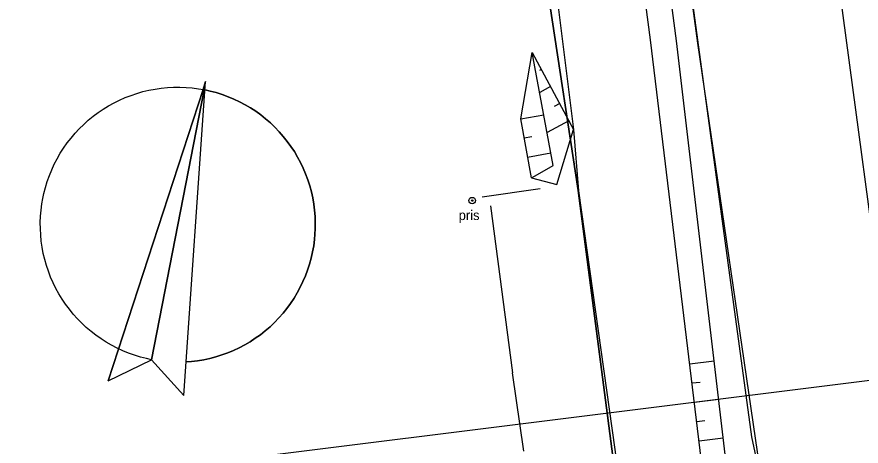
# Model space of a CAD drawing. Extents: x -555887 to -552101, y -1100251 to -1096546.
# Drawn here: x -554065.2 to -553999.8, y -1097845.2 to -1097812 of the extents above; entities that cross this region are included whole.
import ezdxf

# ---------------------------------------------------------------- set-up
doc = ezdxf.new("R2010")
doc.units = 0
for name, color, linetype in [('07_VODOVOD', 7, 'Continuous'), ('PARCELY_silnice', 7, 'Continuous'), ('ROZHLED_ram_legenda_1', 7, 'Continuous'), ('ZSST', 7, 'Continuous'), ('zájem', 7, 'Continuous')]:
    doc.layers.add(name, color=color, linetype=linetype)

msp = doc.modelspace()

# ---------------------------------------------------------------- linework, layer by layer
at = {"layer": '07_VODOVOD'}
msp.add_lwpolyline([(-553936.175, -1098296.386), (-554003.21, -1097797.26), (-554016.58, -1097798.55), (-554021.42, -1097763.29), (-554007.81, -1097761.46), (-554017.883, -1097690.586), (-554019.47, -1097678.04), (-553931.71, -1097666.8), (-553860.51, -1097660.95), (-553851.186, -1097659.979), (-553809.175, -1097658.756), (-553772.306, -1097657.572), (-553745.69, -1097656.809), (-553714.889, -1097655.5), (-553705.569, -1097655.382), (-553663.409, -1097654.214), (-553621.83, -1097652.811), (-553564.872, -1097648.296)], dxfattribs=at)
at = {"layer": 'PARCELY_silnice'}
for points in [[(-553950.34, -1098288.41), (-554001.81, -1097900.62), (-554000.01, -1097890.44), (-554002.33, -1097872.53), (-554008.3, -1097844.49), (-554029.64, -1097687.62), (-554030.91, -1097678.33), (-554047.02, -1097559.88)], [(-554053.21, -1097604.42), (-554046.53, -1097659.36), (-554040.57, -1097685.1), (-554037.19, -1097711.74), (-554032.71, -1097743.24), (-554030.08, -1097764.38), (-554029.42, -1097766.27), (-554026.13, -1097796.62), (-554021.75, -1097825.43), (-554018.68, -1097848.98), (-554014.41, -1097881.75), (-554013.24, -1097889.61), (-554000.89, -1097984.42), (-553998.62, -1098003.87), (-553997.67, -1098021.07), (-553963.01, -1098289.11)]]:
    msp.add_lwpolyline(points, dxfattribs=at)
at = {"layer": 'ROZHLED_ram_legenda_1'}
for p, q in [((-554052.28, -1097841.301), (-554050.582, -1097816.99)), ((-554050.782, -1097817.613), (-554050.582, -1097816.99)), ((-554050.782, -1097817.613), (-554050.582, -1097816.99)), ((-554050.782, -1097817.613), (-554050.582, -1097816.99)), ((-554050.782, -1097817.613), (-554050.582, -1097816.99)), ((-554050.782, -1097817.613), (-554050.582, -1097816.99)), ((-554050.782, -1097817.613), (-554050.582, -1097816.99)), ((-554050.782, -1097817.613), (-554050.582, -1097816.99)), ((-554050.782, -1097817.613), (-554050.582, -1097816.99)), ((-554050.706, -1097817.628), (-554050.582, -1097816.99)), ((-554050.706, -1097817.628), (-554050.582, -1097816.99)), ((-554050.706, -1097817.628), (-554050.582, -1097816.99)), ((-554050.706, -1097817.628), (-554050.582, -1097816.99)), ((-554050.706, -1097817.628), (-554050.582, -1097816.99)), ((-554050.706, -1097817.628), (-554050.582, -1097816.99)), ((-554050.706, -1097817.628), (-554050.582, -1097816.99)), ((-554050.706, -1097817.628), (-554050.582, -1097816.99)), ((-554058.115, -1097840.167), (-554050.782, -1097817.613)), ((-554050.706, -1097817.628), (-554054.768, -1097838.523)), ((-554054.767, -1097838.522), (-554052.28, -1097841.3))]:
    msp.add_line(p, q, dxfattribs=at)
for points in [[(-554134.234, -1097857.005), (-554169.828, -1097572.221), (-553971.373, -1097547.416), (-553935.778, -1097832.201), (-554134.234, -1097857.005)], [(-554134.234, -1097857.005), (-554169.828, -1097572.221), (-553971.373, -1097547.416), (-553935.778, -1097832.201), (-554134.234, -1097857.005)], [(-554054.767, -1097838.522), (-554055.171, -1097838.437), (-554055.637, -1097838.316), (-554056.097, -1097838.174), (-554056.55, -1097838.012), (-554056.995, -1097837.83), (-554057.431, -1097837.627), (-554057.858, -1097837.405), (-554058.275, -1097837.165), (-554058.68, -1097836.905), (-554059.073, -1097836.627), (-554059.453, -1097836.332), (-554059.819, -1097836.02), (-554060.171, -1097835.692), (-554060.507, -1097835.349), (-554060.828, -1097834.99), (-554061.132, -1097834.617), (-554061.419, -1097834.231), (-554061.689, -1097833.832), (-554061.94, -1097833.422), (-554062.172, -1097833.001), (-554062.385, -1097832.569), (-554062.578, -1097832.129), (-554062.751, -1097831.68), (-554062.904, -1097831.224), (-554063.036, -1097830.761), (-554063.146, -1097830.293), (-554063.236, -1097829.82), (-554063.304, -1097829.344), (-554063.351, -1097828.865), (-554063.376, -1097828.385), (-554063.379, -1097827.904), (-554063.36, -1097827.423), (-554063.32, -1097826.943), (-554063.258, -1097826.466), (-554063.186, -1097826.059), (-554063.101, -1097825.655), (-554062.981, -1097825.189), (-554062.84, -1097824.729), (-554062.679, -1097824.276), (-554062.497, -1097823.831), (-554062.295, -1097823.394), (-554062.074, -1097822.967), (-554061.834, -1097822.55), (-554061.575, -1097822.144), (-554061.298, -1097821.751), (-554061.003, -1097821.371), (-554060.692, -1097821.004), (-554060.364, -1097820.652), (-554060.021, -1097820.315), (-554059.663, -1097819.993), (-554059.29, -1097819.689), (-554058.905, -1097819.401), (-554058.506, -1097819.131), (-554058.096, -1097818.88), (-554057.675, -1097818.647), (-554057.244, -1097818.433), (-554056.804, -1097818.239), (-554056.355, -1097818.066), (-554055.899, -1097817.912), (-554055.437, -1097817.78), (-554054.969, -1097817.668), (-554054.496, -1097817.578), (-554054.02, -1097817.509), (-554053.541, -1097817.462), (-554053.061, -1097817.436), (-554052.58, -1097817.433), (-554052.099, -1097817.451), (-554051.62, -1097817.49), (-554051.143, -1097817.551), (-554050.736, -1097817.623)], [(-554050.628, -1097817.644), (-554050.223, -1097817.732), (-554049.756, -1097817.857), (-554049.295, -1097818.003), (-554048.841, -1097818.17), (-554048.395, -1097818.357), (-554047.958, -1097818.565), (-554047.531, -1097818.791), (-554047.114, -1097819.037), (-554046.709, -1097819.302), (-554046.317, -1097819.585), (-554045.938, -1097819.885), (-554045.573, -1097820.203), (-554045.223, -1097820.536), (-554044.888, -1097820.885), (-554044.57, -1097821.249), (-554044.268, -1097821.627), (-554043.984, -1097822.019), (-554043.718, -1097822.422), (-554043.47, -1097822.838), (-554043.242, -1097823.264), (-554043.033, -1097823.701), (-554042.844, -1097824.146), (-554042.676, -1097824.599), (-554042.529, -1097825.06), (-554042.402, -1097825.527), (-554042.297, -1097825.999), (-554042.214, -1097826.475), (-554042.152, -1097826.955), (-554042.112, -1097827.437), (-554042.094, -1097827.92), (-554042.098, -1097828.404), (-554042.12, -1097828.818), (-554042.156, -1097829.23), (-554042.219, -1097829.71), (-554042.304, -1097830.186), (-554042.411, -1097830.658), (-554042.539, -1097831.124), (-554042.688, -1097831.584), (-554042.858, -1097832.037), (-554043.048, -1097832.482), (-554043.258, -1097832.917), (-554043.488, -1097833.343), (-554043.736, -1097833.758), (-554044.004, -1097834.161), (-554044.289, -1097834.551), (-554044.592, -1097834.928), (-554044.912, -1097835.291), (-554045.248, -1097835.639), (-554045.599, -1097835.971), (-554045.965, -1097836.287), (-554046.345, -1097836.586), (-554046.738, -1097836.868), (-554047.144, -1097837.131), (-554047.561, -1097837.376), (-554047.989, -1097837.602), (-554048.427, -1097837.807), (-554048.873, -1097837.993), (-554049.328, -1097838.158), (-554049.789, -1097838.303), (-554050.257, -1097838.426), (-554050.73, -1097838.528), (-554051.207, -1097838.608), (-554051.687, -1097838.667), (-554052.1, -1097838.698)], [(-554052.1, -1097838.698), (-554051.687, -1097838.667), (-554051.207, -1097838.608), (-554050.73, -1097838.528), (-554050.257, -1097838.426), (-554049.789, -1097838.303), (-554049.328, -1097838.158), (-554048.873, -1097837.993), (-554048.427, -1097837.807), (-554047.989, -1097837.602), (-554047.561, -1097837.376), (-554047.144, -1097837.131), (-554046.738, -1097836.868), (-554046.345, -1097836.586), (-554045.965, -1097836.287), (-554045.599, -1097835.971), (-554045.248, -1097835.639), (-554044.912, -1097835.291), (-554044.592, -1097834.928), (-554044.289, -1097834.551), (-554044.004, -1097834.161), (-554043.736, -1097833.758), (-554043.488, -1097833.343), (-554043.258, -1097832.917), (-554043.048, -1097832.482), (-554042.858, -1097832.037), (-554042.688, -1097831.584), (-554042.539, -1097831.124), (-554042.411, -1097830.658), (-554042.304, -1097830.186), (-554042.219, -1097829.71), (-554042.156, -1097829.23), (-554042.12, -1097828.818), (-554042.098, -1097828.404), (-554042.094, -1097827.92), (-554042.112, -1097827.437), (-554042.152, -1097826.955), (-554042.214, -1097826.475), (-554042.297, -1097825.999), (-554042.402, -1097825.527), (-554042.529, -1097825.06), (-554042.676, -1097824.599), (-554042.844, -1097824.146), (-554043.033, -1097823.701), (-554043.242, -1097823.264), (-554043.47, -1097822.838), (-554043.718, -1097822.422), (-554043.984, -1097822.019), (-554044.268, -1097821.627), (-554044.57, -1097821.249), (-554044.888, -1097820.885), (-554045.223, -1097820.536), (-554045.573, -1097820.203), (-554045.938, -1097819.885), (-554046.317, -1097819.585), (-554046.709, -1097819.302), (-554047.114, -1097819.037), (-554047.531, -1097818.791), (-554047.958, -1097818.565), (-554048.395, -1097818.357), (-554048.841, -1097818.17), (-554049.295, -1097818.003), (-554049.756, -1097817.857), (-554050.223, -1097817.732), (-554050.628, -1097817.644)], [(-554052.1, -1097838.698), (-554051.687, -1097838.667), (-554051.207, -1097838.608), (-554050.73, -1097838.528), (-554050.257, -1097838.426), (-554049.789, -1097838.303), (-554049.328, -1097838.158), (-554048.873, -1097837.993), (-554048.427, -1097837.807), (-554047.989, -1097837.602), (-554047.561, -1097837.376), (-554047.144, -1097837.131), (-554046.738, -1097836.868), (-554046.345, -1097836.586), (-554045.965, -1097836.287), (-554045.599, -1097835.971), (-554045.248, -1097835.639), (-554044.912, -1097835.291), (-554044.592, -1097834.928), (-554044.289, -1097834.551), (-554044.004, -1097834.161), (-554043.736, -1097833.758), (-554043.488, -1097833.343), (-554043.258, -1097832.917), (-554043.048, -1097832.482), (-554042.858, -1097832.037), (-554042.688, -1097831.584), (-554042.539, -1097831.124), (-554042.411, -1097830.658), (-554042.304, -1097830.186), (-554042.219, -1097829.71), (-554042.156, -1097829.23), (-554042.12, -1097828.818), (-554042.098, -1097828.404), (-554042.094, -1097827.92), (-554042.112, -1097827.437), (-554042.152, -1097826.955), (-554042.214, -1097826.475), (-554042.297, -1097825.999), (-554042.402, -1097825.527), (-554042.529, -1097825.06), (-554042.676, -1097824.599), (-554042.844, -1097824.146), (-554043.033, -1097823.701), (-554043.242, -1097823.264), (-554043.47, -1097822.838), (-554043.718, -1097822.422), (-554043.984, -1097822.019), (-554044.268, -1097821.627), (-554044.57, -1097821.249), (-554044.888, -1097820.885), (-554045.223, -1097820.536), (-554045.573, -1097820.203), (-554045.938, -1097819.885), (-554046.317, -1097819.585), (-554046.709, -1097819.302), (-554047.114, -1097819.037), (-554047.531, -1097818.791), (-554047.958, -1097818.565), (-554048.395, -1097818.357), (-554048.841, -1097818.17), (-554049.295, -1097818.003), (-554049.756, -1097817.857), (-554050.223, -1097817.732), (-554050.628, -1097817.644)], [(-554052.1, -1097838.698), (-554051.687, -1097838.667), (-554051.207, -1097838.608), (-554050.73, -1097838.528), (-554050.257, -1097838.426), (-554049.789, -1097838.303), (-554049.328, -1097838.158), (-554048.873, -1097837.993), (-554048.427, -1097837.807), (-554047.989, -1097837.602), (-554047.561, -1097837.376), (-554047.144, -1097837.131), (-554046.738, -1097836.868), (-554046.345, -1097836.586), (-554045.965, -1097836.287), (-554045.599, -1097835.971), (-554045.248, -1097835.639), (-554044.912, -1097835.291), (-554044.592, -1097834.928), (-554044.289, -1097834.551), (-554044.004, -1097834.161), (-554043.736, -1097833.758), (-554043.488, -1097833.343), (-554043.258, -1097832.917), (-554043.048, -1097832.482), (-554042.858, -1097832.037), (-554042.688, -1097831.584), (-554042.539, -1097831.124), (-554042.411, -1097830.658), (-554042.304, -1097830.186), (-554042.219, -1097829.71), (-554042.156, -1097829.23), (-554042.12, -1097828.818), (-554042.098, -1097828.404), (-554042.094, -1097827.92), (-554042.112, -1097827.437), (-554042.152, -1097826.955), (-554042.214, -1097826.475), (-554042.297, -1097825.999), (-554042.402, -1097825.527), (-554042.529, -1097825.06), (-554042.676, -1097824.599), (-554042.844, -1097824.146), (-554043.033, -1097823.701), (-554043.242, -1097823.264), (-554043.47, -1097822.838), (-554043.718, -1097822.422), (-554043.984, -1097822.019), (-554044.268, -1097821.627), (-554044.57, -1097821.249), (-554044.888, -1097820.885), (-554045.223, -1097820.536), (-554045.573, -1097820.203), (-554045.938, -1097819.885), (-554046.317, -1097819.585), (-554046.709, -1097819.302), (-554047.114, -1097819.037), (-554047.531, -1097818.791), (-554047.958, -1097818.565), (-554048.395, -1097818.357), (-554048.841, -1097818.17), (-554049.295, -1097818.003), (-554049.756, -1097817.857), (-554050.223, -1097817.732), (-554050.628, -1097817.644)], [(-554052.1, -1097838.698), (-554051.687, -1097838.667), (-554051.207, -1097838.608), (-554050.73, -1097838.528), (-554050.257, -1097838.426), (-554049.789, -1097838.303), (-554049.328, -1097838.158), (-554048.873, -1097837.993), (-554048.427, -1097837.807), (-554047.989, -1097837.602), (-554047.561, -1097837.376), (-554047.144, -1097837.131), (-554046.738, -1097836.868), (-554046.345, -1097836.586), (-554045.965, -1097836.287), (-554045.599, -1097835.971), (-554045.248, -1097835.639), (-554044.912, -1097835.291), (-554044.592, -1097834.928), (-554044.289, -1097834.551), (-554044.004, -1097834.161), (-554043.736, -1097833.758), (-554043.488, -1097833.343), (-554043.258, -1097832.917), (-554043.048, -1097832.482), (-554042.858, -1097832.037), (-554042.688, -1097831.584), (-554042.539, -1097831.124), (-554042.411, -1097830.658), (-554042.304, -1097830.186), (-554042.219, -1097829.71), (-554042.156, -1097829.23), (-554042.12, -1097828.818), (-554042.098, -1097828.404), (-554042.094, -1097827.92), (-554042.112, -1097827.437), (-554042.152, -1097826.955), (-554042.214, -1097826.475), (-554042.297, -1097825.999), (-554042.402, -1097825.527), (-554042.529, -1097825.06), (-554042.676, -1097824.599), (-554042.844, -1097824.146), (-554043.033, -1097823.701), (-554043.242, -1097823.264), (-554043.47, -1097822.838), (-554043.718, -1097822.422), (-554043.984, -1097822.019), (-554044.268, -1097821.627), (-554044.57, -1097821.249), (-554044.888, -1097820.885), (-554045.223, -1097820.536), (-554045.573, -1097820.203), (-554045.938, -1097819.885), (-554046.317, -1097819.585), (-554046.709, -1097819.302), (-554047.114, -1097819.037), (-554047.531, -1097818.791), (-554047.958, -1097818.565), (-554048.395, -1097818.357), (-554048.841, -1097818.17), (-554049.295, -1097818.003), (-554049.756, -1097817.857), (-554050.223, -1097817.732), (-554050.628, -1097817.644)], [(-554052.1, -1097838.698), (-554051.687, -1097838.667), (-554051.207, -1097838.608), (-554050.73, -1097838.528), (-554050.257, -1097838.426), (-554049.789, -1097838.303), (-554049.328, -1097838.158), (-554048.873, -1097837.993), (-554048.427, -1097837.807), (-554047.989, -1097837.602), (-554047.561, -1097837.376), (-554047.144, -1097837.131), (-554046.738, -1097836.868), (-554046.345, -1097836.586), (-554045.965, -1097836.287), (-554045.599, -1097835.971), (-554045.248, -1097835.639), (-554044.912, -1097835.291), (-554044.592, -1097834.928), (-554044.289, -1097834.551), (-554044.004, -1097834.161), (-554043.736, -1097833.758), (-554043.488, -1097833.343), (-554043.258, -1097832.917), (-554043.048, -1097832.482), (-554042.858, -1097832.037), (-554042.688, -1097831.584), (-554042.539, -1097831.124), (-554042.411, -1097830.658), (-554042.304, -1097830.186), (-554042.219, -1097829.71), (-554042.156, -1097829.23), (-554042.12, -1097828.818), (-554042.098, -1097828.404), (-554042.094, -1097827.92), (-554042.112, -1097827.437), (-554042.152, -1097826.955), (-554042.214, -1097826.475), (-554042.297, -1097825.999), (-554042.402, -1097825.527), (-554042.529, -1097825.06), (-554042.676, -1097824.599), (-554042.844, -1097824.146), (-554043.033, -1097823.701), (-554043.242, -1097823.264), (-554043.47, -1097822.838), (-554043.718, -1097822.422), (-554043.984, -1097822.019), (-554044.268, -1097821.627), (-554044.57, -1097821.249), (-554044.888, -1097820.885), (-554045.223, -1097820.536), (-554045.573, -1097820.203), (-554045.938, -1097819.885), (-554046.317, -1097819.585), (-554046.709, -1097819.302), (-554047.114, -1097819.037), (-554047.531, -1097818.791), (-554047.958, -1097818.565), (-554048.395, -1097818.357), (-554048.841, -1097818.17), (-554049.295, -1097818.003), (-554049.756, -1097817.857), (-554050.223, -1097817.732), (-554050.628, -1097817.644)], [(-554052.1, -1097838.698), (-554051.687, -1097838.667), (-554051.207, -1097838.608), (-554050.73, -1097838.528), (-554050.257, -1097838.426), (-554049.789, -1097838.303), (-554049.328, -1097838.158), (-554048.873, -1097837.993), (-554048.427, -1097837.807), (-554047.989, -1097837.602), (-554047.561, -1097837.376), (-554047.144, -1097837.131), (-554046.738, -1097836.868), (-554046.345, -1097836.586), (-554045.965, -1097836.287), (-554045.599, -1097835.971), (-554045.248, -1097835.639), (-554044.912, -1097835.291), (-554044.592, -1097834.928), (-554044.289, -1097834.551), (-554044.004, -1097834.161), (-554043.736, -1097833.758), (-554043.488, -1097833.343), (-554043.258, -1097832.917), (-554043.048, -1097832.482), (-554042.858, -1097832.037), (-554042.688, -1097831.584), (-554042.539, -1097831.124), (-554042.411, -1097830.658), (-554042.304, -1097830.186), (-554042.219, -1097829.71), (-554042.156, -1097829.23), (-554042.12, -1097828.818), (-554042.098, -1097828.404), (-554042.094, -1097827.92), (-554042.112, -1097827.437), (-554042.152, -1097826.955), (-554042.214, -1097826.475), (-554042.297, -1097825.999), (-554042.402, -1097825.527), (-554042.529, -1097825.06), (-554042.676, -1097824.599), (-554042.844, -1097824.146), (-554043.033, -1097823.701), (-554043.242, -1097823.264), (-554043.47, -1097822.838), (-554043.718, -1097822.422), (-554043.984, -1097822.019), (-554044.268, -1097821.627), (-554044.57, -1097821.249), (-554044.888, -1097820.885), (-554045.223, -1097820.536), (-554045.573, -1097820.203), (-554045.938, -1097819.885), (-554046.317, -1097819.585), (-554046.709, -1097819.302), (-554047.114, -1097819.037), (-554047.531, -1097818.791), (-554047.958, -1097818.565), (-554048.395, -1097818.357), (-554048.841, -1097818.17), (-554049.295, -1097818.003), (-554049.756, -1097817.857), (-554050.223, -1097817.732), (-554050.628, -1097817.644)], [(-554052.1, -1097838.698), (-554051.687, -1097838.667), (-554051.207, -1097838.608), (-554050.73, -1097838.528), (-554050.257, -1097838.426), (-554049.789, -1097838.303), (-554049.328, -1097838.158), (-554048.873, -1097837.993), (-554048.427, -1097837.807), (-554047.989, -1097837.602), (-554047.561, -1097837.376), (-554047.144, -1097837.131), (-554046.738, -1097836.868), (-554046.345, -1097836.586), (-554045.965, -1097836.287), (-554045.599, -1097835.971), (-554045.248, -1097835.639), (-554044.912, -1097835.291), (-554044.592, -1097834.928), (-554044.289, -1097834.551), (-554044.004, -1097834.161), (-554043.736, -1097833.758), (-554043.488, -1097833.343), (-554043.258, -1097832.917), (-554043.048, -1097832.482), (-554042.858, -1097832.037), (-554042.688, -1097831.584), (-554042.539, -1097831.124), (-554042.411, -1097830.658), (-554042.304, -1097830.186), (-554042.219, -1097829.71), (-554042.156, -1097829.23), (-554042.12, -1097828.818), (-554042.098, -1097828.404), (-554042.094, -1097827.92), (-554042.112, -1097827.437), (-554042.152, -1097826.955), (-554042.214, -1097826.475), (-554042.297, -1097825.999), (-554042.402, -1097825.527), (-554042.529, -1097825.06), (-554042.676, -1097824.599), (-554042.844, -1097824.146), (-554043.033, -1097823.701), (-554043.242, -1097823.264), (-554043.47, -1097822.838), (-554043.718, -1097822.422), (-554043.984, -1097822.019), (-554044.268, -1097821.627), (-554044.57, -1097821.249), (-554044.888, -1097820.885), (-554045.223, -1097820.536), (-554045.573, -1097820.203), (-554045.938, -1097819.885), (-554046.317, -1097819.585), (-554046.709, -1097819.302), (-554047.114, -1097819.037), (-554047.531, -1097818.791), (-554047.958, -1097818.565), (-554048.395, -1097818.357), (-554048.841, -1097818.17), (-554049.295, -1097818.003), (-554049.756, -1097817.857), (-554050.223, -1097817.732), (-554050.628, -1097817.644)]]:
    msp.add_lwpolyline(points, dxfattribs=at)
for points in [[(-554050.784, -1097817.613), (-554050.764, -1097817.617), (-554050.745, -1097817.621), (-554050.725, -1097817.625), (-554050.706, -1097817.628), (-554050.706, -1097817.628), (-554050.582, -1097816.99), (-554050.782, -1097817.613), (-554050.782, -1097817.613)], [(-554050.784, -1097817.613), (-554050.764, -1097817.617), (-554050.745, -1097817.621), (-554050.725, -1097817.625), (-554050.706, -1097817.628), (-554050.706, -1097817.628), (-554050.582, -1097816.99), (-554050.782, -1097817.613), (-554050.782, -1097817.613)], [(-554050.784, -1097817.613), (-554050.764, -1097817.617), (-554050.745, -1097817.621), (-554050.725, -1097817.625), (-554050.706, -1097817.628), (-554050.706, -1097817.628), (-554050.582, -1097816.99), (-554050.782, -1097817.613), (-554050.782, -1097817.613)], [(-554050.784, -1097817.613), (-554050.764, -1097817.617), (-554050.745, -1097817.621), (-554050.725, -1097817.625), (-554050.706, -1097817.628), (-554050.706, -1097817.628), (-554050.582, -1097816.99), (-554050.782, -1097817.613), (-554050.782, -1097817.613)], [(-554050.784, -1097817.613), (-554050.764, -1097817.617), (-554050.745, -1097817.621), (-554050.725, -1097817.625), (-554050.706, -1097817.628), (-554050.706, -1097817.628), (-554050.582, -1097816.99), (-554050.782, -1097817.613), (-554050.782, -1097817.613)], [(-554050.784, -1097817.613), (-554050.764, -1097817.617), (-554050.745, -1097817.621), (-554050.725, -1097817.625), (-554050.706, -1097817.628), (-554050.706, -1097817.628), (-554050.582, -1097816.99), (-554050.782, -1097817.613), (-554050.782, -1097817.613)], [(-554050.784, -1097817.613), (-554050.764, -1097817.617), (-554050.745, -1097817.621), (-554050.725, -1097817.625), (-554050.706, -1097817.628), (-554050.706, -1097817.628), (-554050.582, -1097816.99), (-554050.782, -1097817.613), (-554050.782, -1097817.613)], [(-554050.784, -1097817.613), (-554050.764, -1097817.617), (-554050.745, -1097817.621), (-554050.725, -1097817.625), (-554050.706, -1097817.628), (-554050.706, -1097817.628), (-554050.582, -1097816.99), (-554050.782, -1097817.613), (-554050.782, -1097817.613)], [(-554058.115, -1097840.167), (-554054.768, -1097838.523), (-554050.706, -1097817.628), (-554050.782, -1097817.613)], [(-554058.115, -1097840.167), (-554054.768, -1097838.523), (-554050.706, -1097817.628), (-554050.782, -1097817.613)], [(-554058.115, -1097840.167), (-554054.768, -1097838.523), (-554050.706, -1097817.628), (-554050.782, -1097817.613)], [(-554058.115, -1097840.167), (-554054.768, -1097838.523), (-554050.706, -1097817.628), (-554050.782, -1097817.613)], [(-554058.115, -1097840.167), (-554054.768, -1097838.523), (-554050.706, -1097817.628), (-554050.782, -1097817.613)], [(-554058.115, -1097840.167), (-554054.768, -1097838.523), (-554050.706, -1097817.628), (-554050.782, -1097817.613)], [(-554058.115, -1097840.167), (-554054.768, -1097838.523), (-554050.706, -1097817.628), (-554050.782, -1097817.613)], [(-554058.115, -1097840.167), (-554054.768, -1097838.523), (-554050.706, -1097817.628), (-554050.782, -1097817.613)]]:
    msp.add_lwpolyline(points, close=True, dxfattribs=at)
at = {"layer": 'ZSST'}
for p, q in [((-554014.15, -1097813.85), (-554020.4, -1097765.81)), ((-554010.01, -1097848.87), (-554014.15, -1097813.85)), ((-554025.3, -1097814.74), (-554025.3, -1097814.74)), ((-554024.593, -1097816.063), (-554024.733, -1097816.138)), ((-554023.886, -1097817.386), (-554024.728, -1097817.836)), ((-554023.179, -1097818.709), (-554023.6, -1097818.933)), ((-554026.2, -1097819.89), (-554024.408, -1097819.565)), ((-554022.472, -1097820.032), (-554024.155, -1097820.931)), ((-554025.932, -1097821.366), (-554025.334, -1097821.257)), ((-554025.664, -1097822.842), (-554023.862, -1097822.514)), ((-554024.69, -1097825.29), (-554029.19, -1097825.95)), ((-554028.54, -1097826.62), (-554026.84, -1097839.55)), ((-554013.117, -1097838.836), (-554011.223, -1097838.607)), ((-554025.95, -1097845.61), (-554026.84, -1097839.55)), ((-554012.936, -1097840.325), (-554012.307, -1097840.249)), ((-554012.756, -1097841.815), (-554010.871, -1097841.586)), ((-554012.575, -1097843.304), (-554011.949, -1097843.228)), ((-554012.394, -1097844.793), (-554010.519, -1097844.565))]:
    msp.add_line(p, q, dxfattribs=at)
for points in [[(-554004.38, -1097907.95), (-554007.16, -1097886.83), (-554009.83, -1097866.73), (-554011.06, -1097855.79), (-554016.16, -1097813.76), (-554022.49, -1097765.68), (-554022.89, -1097762.85), (-554033.17, -1097686.07)], [(-554038.93, -1097695.81), (-554036.68, -1097711.27), (-554032.37, -1097743.21), (-554029.29, -1097765.74), (-554028.18, -1097773.76), (-554026.94, -1097782.88), (-554024.58, -1097801.37), (-554023.29, -1097811.21), (-554022.11, -1097820.71), (-554021.72, -1097825.46), (-554018.91, -1097845.48), (-554014.76, -1097877), (-554018.4, -1097877.46), (-554019.08, -1097877.63)], [(-554001.76, -1097874.55), (-554003.79, -1097865.23), (-554007.51, -1097848.12), (-554012.49, -1097814.02), (-554018.94, -1097766.27), (-553994.65, -1097762.99), (-553948.26, -1097757.68), (-553920.88, -1097754.01)], [(-554025.37, -1097824.46), (-554026.2, -1097819.89), (-554025.3, -1097814.74), (-554022.11, -1097820.71)], [(-554025.37, -1097824.46), (-554024.89, -1097824.19), (-554023.68, -1097823.5), (-554025.3, -1097814.74)], [(-554025.37, -1097824.46), (-554023.39, -1097824.97), (-554022.11, -1097820.71)]]:
    msp.add_lwpolyline(points, dxfattribs=at)
for radius in [0.25, 0.05]:
    msp.add_circle((-554029.95, -1097826.21), radius, dxfattribs=at)
at = {"layer": 'zájem'}
for points in [[(-554000.89, -1097984.42), (-554013.24, -1097889.61), (-554014.41, -1097881.75), (-554018.68, -1097848.98), (-554021.75, -1097825.43), (-554026.13, -1097796.62), (-554029.42, -1097766.27), (-554030.08, -1097764.38), (-554032.71, -1097743.24), (-554037.19, -1097711.74), (-554040.57, -1097685.1), (-554046.53, -1097659.36), (-554053.21, -1097604.42)], [(-554053.21, -1097604.42), (-554046.53, -1097659.36), (-554040.57, -1097685.1), (-554037.19, -1097711.74), (-554032.71, -1097743.24), (-554030.08, -1097764.38), (-554029.42, -1097766.27), (-554026.13, -1097796.62), (-554021.75, -1097825.43), (-554018.68, -1097848.98), (-554014.41, -1097881.75), (-554013.24, -1097889.61), (-554000.89, -1097984.42)]]:
    msp.add_lwpolyline(points, dxfattribs=at)

# ---------------------------------------------------------------- texts
at = {"layer": 'ZSST'}
msp.add_text('pris', height=0.75, dxfattribs=at).set_placement((-554030.999, -1097827.715))

doc.saveas('drawing.dxf')
